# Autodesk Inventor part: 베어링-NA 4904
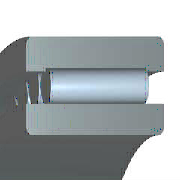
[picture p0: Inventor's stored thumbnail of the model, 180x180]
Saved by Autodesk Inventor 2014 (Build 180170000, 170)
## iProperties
IsCustomPart: 1
Company: 한국ATC센터
Created: 2009-02
Part Number: 베어링-NA 4904
Material: 강, 연강
Description: 니들 롤러 베어링 - 경계 치수 및 공차
Document SubType Name: Modeling
Standard: KS B 2029
Designer: KYOUNG IL JANG
Standards Organization: KS
Language: ko-KR
Size Designation: NA 4904 - 20 x 37 x 17
Categories: <MemberInstance><Categories><Category DisplayName="샤프트 부품" InternalName="7f7aeb1f-a693-4053-b835-cee3144e0d98" Mnemonic="SHFT"><Category DisplayName="베어링" Inter
Density: 7.86 g/cm^3
Mass: 73.0303 g
Surface Area: 90.2463 cm^2
Volume: 9.29139 cm^3
Vendor: CBT Solutions
Appearance: 강철
Author: KYOUNG IL JANG
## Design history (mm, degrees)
sketch "스케치"
  geometry: L1 (2.429, 16)-(14.571, 16); L2 (14.571, 16)-(14.571, 12.5); L3 (17, 12.5)-(0, 12.5); L4 (2.429, 12.5)-(2.429, 16); L5 (2.429, 14.25)-(14.571, 14.25); L6 (8.5, 14.25)-(8.5, 12.5); L7 (0, 10)-(17, 10); L8 (0, 18.5)-(17, 18.5); L9 (17, 10)-(17, 12.5); L10 (17, 15.65)-(17, 18.5); L11 (2.429, 15.65)-(0, 15.65); L12 (14.571, 15.65)-(17, 15.65); L13 (-6, 0)-(36, 0) reference; L14 (0, -1.9)-(0, 14.9) reference
  constraints: 24 end point, 8 point on line, 3 midpoint, 3 parallel, 3 perpendicular, 2 symmetric about line, 1 horizontal, 1 other
  dimensions: "d6" = 20 diameter of L7 L13 (= WD); "d7" = 25 diameter of L3 L13 (= KID1); "d8" = 37 diameter of L8 L13 (= BD); "d9" = 28.5 diameter of L6.start L13 (= 0.5 x WD + 0.5 x BD); "d10" = 31.3 diameter of L12 L13 (= 0.9 x BD + 0.9 x WD - 0.8 x KID1); "d11" = 32 diameter of L1 L13 (= BD + WD - KID1); "d12" = 2.42857 distance between parallel lines of L14 L4 (= 0.142857 x KB); "d13" = 17 distance between parallel lines of L14 L9 (= KB); "d14" = 14.57143 distance between parallel lines of L14 L2 (= 0.857143 x KB)
revolve "본체" stored, may be unused: angle "d17" = 90 deg
revolve "롤러" stored, may be unused: angle "d18" = 90 deg
pattern_circular "IDS_ARRAYROLLER[SIMPL:T]" dims angle "d2" = 360 deg
body "Solid1"
fillet "모깎기1" dims "d0" = 0.3 (= KRS)
other parameters: "WD" = 20 [user parameter; used in 6 equation terms], "BD" = 37 [user parameter; used in 6 equation terms], "KB" = 17 [user parameter; used in 3 equation terms], "KID1" = 25 [user parameter; used in 4 equation terms], "KRS" = 0.3 [user parameter; used in 1 equation term], "d3" = 0, "d4" = 0, "d5" = 0, "d15" = 0, "d16" = 0, "BC0" = 2.36e+07 [user parameter], "BBA" = 0 [user parameter], "BC" = 1.9e+07 [user parameter], "BR" = 18.5 (= 0.5 x BD) [user parameter]
